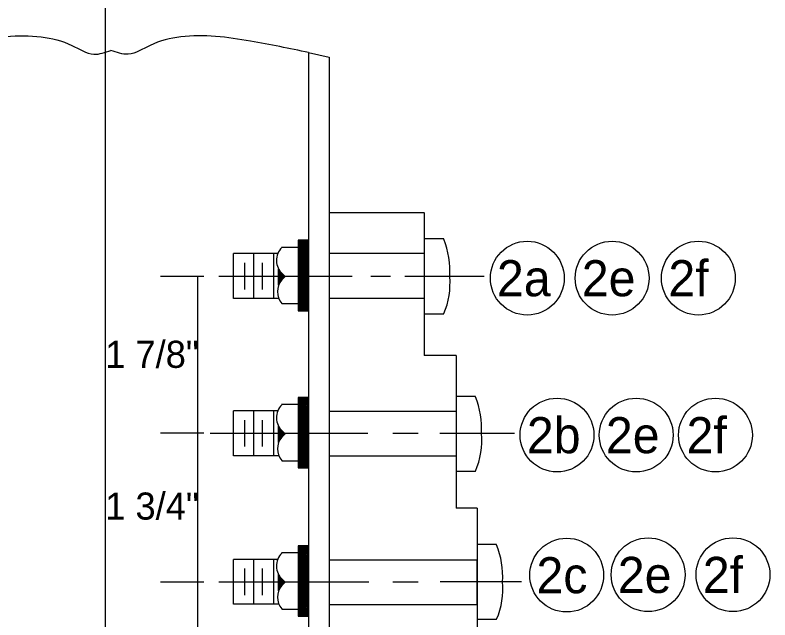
# Model space of a CAD drawing. Extents: x 12.3 to 19.6, y 18.8 to 29.6.
# Drawn here: x 15.033 to 16.703, y 23.308 to 24.647 of the extents above; entities that cross this region are included whole.
import ezdxf

# ---------------------------------------------------------------- set-up
doc = ezdxf.new("R2010")
doc.units = 0
for name, color, linetype in [('BORD-LINE', 7, 'Continuous'), ('DETL-DIMS', 7, 'Continuous'), ('DETL-LINE', 7, 'Continuous')]:
    doc.layers.add(name, color=color, linetype=linetype)

msp = doc.modelspace()

# ---------------------------------------------------------------- linework, layer by layer
at = {"layer": 'BORD-LINE'}
for centre in [(16.1665, 24.0647), (16.3542, 24.0647), (16.5451, 24.0647), (16.2324, 23.7172), (16.4075, 23.7172), (16.5829, 23.7172), (16.2537, 23.407), (16.4339, 23.4079), (16.6216, 23.4079)]:
    msp.add_circle(centre, 0.0817, dxfattribs=at)
at = {"layer": 'DETL-DIMS'}
for p, q in [((15.2325, 25.0229), (15.2325, 22.8206)), ((15.4511, 24.068), (15.3552, 24.068)), ((15.4368, 24.068), (15.4368, 22.9003)), ((15.7792, 24.068), (15.4843, 24.068)), ((15.8638, 24.068), (15.8206, 24.068)), ((16.0712, 24.068), (15.8955, 24.068)), ((15.4511, 23.721), (15.3552, 23.721)), ((15.4645, 23.721), (15.8134, 23.721)), ((15.8691, 23.721), (15.9249, 23.721)), ((15.9728, 23.721), (16.1383, 23.721)), ((15.4511, 23.3913), (15.3552, 23.3913)), ((15.627, 23.3913), (15.4843, 23.3913)), ((15.8158, 23.3913), (15.5089, 23.3913)), ((15.9249, 23.3913), (15.8691, 23.3913)), ((16.1538, 23.3919), (15.9734, 23.3919))]:
    msp.add_line(p, q, dxfattribs=at)
at = {"layer": 'DETL-LINE'}
for p, q in [((15.6827, 24.5643), (15.6827, 22.9003)), ((15.7282, 24.5542), (15.7282, 22.9003)), ((15.9387, 24.2095), (15.7282, 24.2095)), ((15.9387, 24.2095), (15.9387, 24.2101)), ((15.9387, 24.2095), (15.9387, 23.8936)), ((15.6143, 24.119), (15.5167, 24.119)), ((15.5167, 24.0195), (15.5167, 24.119)), ((15.5611, 24.0195), (15.5611, 24.1184)), ((15.6054, 24.0195), (15.6054, 24.1184)), ((15.9387, 24.119), (15.7282, 24.119)), ((15.5412, 24.0398), (15.5412, 24.0986)), ((15.5808, 24.0398), (15.5808, 24.0986)), ((15.6162, 24.0488), (15.6162, 24.0848)), ((15.63, 24.0675), (15.6162, 24.0812)), ((15.63, 24.0668), (15.6162, 24.0795)), ((15.6287, 24.0662), (15.6162, 24.0765)), ((15.6282, 24.0656), (15.6162, 24.074)), ((15.627, 24.0645), (15.6162, 24.0722)), ((15.6263, 24.0632), (15.6162, 24.0705)), ((15.6252, 24.0626), (15.6162, 24.0686)), ((15.624, 24.0615), (15.6162, 24.0668)), ((15.6306, 24.068), (15.6233, 24.0608)), ((15.6306, 24.068), (15.6252, 24.074)), ((15.6228, 24.0602), (15.6162, 24.065)), ((15.6222, 24.0591), (15.6162, 24.0632)), ((15.621, 24.0578), (15.6162, 24.0615)), ((15.6203, 24.0566), (15.6162, 24.0596)), ((15.6198, 24.0555), (15.6162, 24.0578)), ((15.6186, 24.0536), (15.6162, 24.0561)), ((15.618, 24.0525), (15.6162, 24.0542)), ((15.6173, 24.0512), (15.6162, 24.0525)), ((15.6168, 24.0501), (15.6162, 24.0506)), ((15.6168, 24.0195), (15.5167, 24.0195)), ((15.9387, 24.0195), (15.7282, 24.0195)), ((16.0088, 23.8936), (15.9387, 23.8936)), ((16.0088, 23.8936), (16.0088, 23.555)), ((15.6143, 23.7708), (15.5167, 23.7708)), ((15.5167, 23.6712), (15.5167, 23.7708)), ((15.5611, 23.6712), (15.5611, 23.7701)), ((15.6054, 23.6712), (15.6054, 23.7701)), ((16.0088, 23.7695), (15.7282, 23.7695)), ((15.5412, 23.6916), (15.5412, 23.7504)), ((15.5808, 23.6916), (15.5808, 23.7504)), ((15.6162, 23.7006), (15.6162, 23.7365)), ((15.63, 23.7191), (15.6162, 23.7324)), ((15.6293, 23.7186), (15.6162, 23.73)), ((15.6282, 23.7174), (15.6162, 23.7275)), ((15.6276, 23.7168), (15.6162, 23.7251)), ((15.627, 23.7161), (15.6162, 23.7234)), ((15.6258, 23.715), (15.6162, 23.7215)), ((15.6252, 23.7144), (15.6162, 23.7198)), ((15.624, 23.7131), (15.6162, 23.718)), ((15.6228, 23.7114), (15.6162, 23.7161)), ((15.6306, 23.7198), (15.6233, 23.7126)), ((15.6306, 23.7198), (15.6246, 23.7258)), ((15.6216, 23.7101), (15.6162, 23.7144)), ((15.621, 23.7096), (15.6162, 23.7126)), ((15.6203, 23.7084), (15.6162, 23.7114)), ((15.6192, 23.7071), (15.6162, 23.7096)), ((15.6186, 23.706), (15.6162, 23.7078)), ((15.618, 23.7041), (15.6162, 23.706)), ((15.6173, 23.703), (15.6162, 23.7041)), ((15.6168, 23.7018), (15.6162, 23.7024)), ((15.6168, 23.6712), (15.5167, 23.6712)), ((16.0088, 23.6706), (15.7282, 23.6706)), ((16.0556, 23.555), (16.0088, 23.555)), ((16.0556, 23.555), (16.0556, 23.275)), ((15.6143, 23.4417), (15.5167, 23.4417)), ((15.5167, 23.3427), (15.5167, 23.4417)), ((15.5611, 23.3427), (15.5611, 23.4417)), ((15.6054, 23.3427), (15.6054, 23.4417)), ((16.0556, 23.4404), (15.7282, 23.4404)), ((16.0556, 23.4417), (16.0556, 23.3403)), ((16.0556, 23.3409), (16.0556, 23.4392)), ((15.5412, 23.3625), (15.5412, 23.4218)), ((15.5808, 23.3625), (15.5808, 23.4218)), ((15.6162, 23.3721), (15.6162, 23.4081)), ((15.63, 23.3907), (15.6162, 23.4044)), ((15.63, 23.3907), (15.6162, 23.4027)), ((15.6293, 23.3901), (15.6162, 23.4009)), ((15.6287, 23.3889), (15.6162, 23.3979)), ((15.6276, 23.3877), (15.6162, 23.3954)), ((15.6258, 23.3865), (15.6162, 23.3937)), ((15.6252, 23.3853), (15.6162, 23.3913)), ((15.624, 23.3841), (15.6162, 23.3895)), ((15.6228, 23.3829), (15.6162, 23.3877)), ((15.6216, 23.3817), (15.6162, 23.3859)), ((15.621, 23.3805), (15.6162, 23.3835)), ((15.6198, 23.3793), (15.6162, 23.3823)), ((15.6306, 23.3913), (15.6233, 23.3841)), ((15.6306, 23.3913), (15.6246, 23.3973)), ((15.6192, 23.3781), (15.6162, 23.3805)), ((15.6186, 23.3769), (15.6162, 23.3787)), ((15.618, 23.3757), (15.6162, 23.3775)), ((15.6173, 23.3745), (15.6162, 23.3757)), ((15.6168, 23.3733), (15.6162, 23.3739)), ((15.6168, 23.3427), (15.5167, 23.3427)), ((16.0556, 23.3409), (15.7282, 23.3409))]:
    msp.add_line(p, q, dxfattribs=at)
for points in [[(15.6827, 24.5643), (15.7282, 24.5542)], [(15.9818, 24.1507), (15.9818, 24.1514), (15.9387, 24.1514), (15.9387, 23.9859), (15.9818, 23.9859)], [(15.6827, 24.149), (15.6593, 24.149), (15.6593, 23.9925), (15.6827, 23.9925)], [(15.6827, 24.1466), (15.6611, 24.1466), (15.6611, 23.9949), (15.6827, 23.9949)], [(15.6827, 24.1447), (15.6635, 24.1447), (15.6635, 23.9973), (15.6827, 23.9973)], [(15.6827, 24.1424), (15.6653, 24.1424), (15.6653, 23.9991), (15.6827, 23.9991)], [(15.6827, 24.14), (15.6677, 24.14), (15.6677, 24.0015), (15.6827, 24.0015)], [(15.6827, 24.1381), (15.6701, 24.1381), (15.6701, 24.0033), (15.6827, 24.0033)], [(15.6827, 24.1357), (15.672, 24.1357), (15.672, 24.0057), (15.6827, 24.0057)], [(15.6593, 24.1327), (15.6228, 24.1327)], [(15.6827, 24.1334), (15.6743, 24.1334), (15.6743, 24.0081), (15.6827, 24.0081)], [(15.6827, 24.1316), (15.6767, 24.1316), (15.6767, 24.0099), (15.6827, 24.0099)], [(15.6827, 24.1292), (15.6785, 24.1292), (15.6785, 24.0123), (15.6827, 24.0123)], [(15.6827, 24.1274), (15.6809, 24.1274), (15.6809, 24.0147), (15.6827, 24.0147)], [(15.6233, 24.0087), (15.6593, 24.0087)], [(15.6827, 23.8007), (15.6593, 23.8007), (15.6593, 23.6449), (15.6827, 23.6449)], [(16.0519, 23.8019), (16.0519, 23.8025), (16.0088, 23.8025), (16.0088, 23.637), (16.0519, 23.637)], [(15.6593, 23.7845), (15.6228, 23.7845)], [(15.6827, 23.7983), (15.6611, 23.7983), (15.6611, 23.6466), (15.6827, 23.6466)], [(15.6827, 23.7965), (15.6635, 23.7965), (15.6635, 23.649), (15.6827, 23.649)], [(15.6827, 23.7941), (15.6653, 23.7941), (15.6653, 23.6509), (15.6827, 23.6509)], [(15.6827, 23.7917), (15.6677, 23.7917), (15.6677, 23.6532), (15.6827, 23.6532)], [(15.6827, 23.7899), (15.6701, 23.7899), (15.6701, 23.6556), (15.6827, 23.6556)], [(15.6827, 23.7875), (15.672, 23.7875), (15.672, 23.6574), (15.6827, 23.6574)], [(15.6827, 23.7857), (15.6743, 23.7857), (15.6743, 23.6599), (15.6827, 23.6599)], [(15.6827, 23.7833), (15.6761, 23.7833), (15.6761, 23.6622), (15.6827, 23.6622)], [(15.6827, 23.7809), (15.6785, 23.7809), (15.6785, 23.664), (15.6827, 23.664)], [(15.6827, 23.7791), (15.6809, 23.7791), (15.6809, 23.6664), (15.6827, 23.6664)], [(15.6233, 23.6604), (15.6593, 23.6604)], [(15.6827, 23.4722), (15.6593, 23.4722), (15.6593, 23.3158), (15.6827, 23.3158)], [(15.6827, 23.4698), (15.6611, 23.4698), (15.6611, 23.3182), (15.6827, 23.3182)], [(15.6827, 23.4674), (15.6635, 23.4674), (15.6635, 23.3199), (15.6827, 23.3199)], [(15.6827, 23.4656), (15.6653, 23.4656), (15.6653, 23.3224), (15.6827, 23.3224)], [(16.0987, 23.474), (16.0987, 23.4746), (16.0556, 23.4746), (16.0556, 23.3092), (16.0987, 23.3092)], [(15.6593, 23.4561), (15.6228, 23.4561)], [(15.6827, 23.4632), (15.6677, 23.4632), (15.6677, 23.3248), (15.6827, 23.3248)], [(15.6827, 23.4608), (15.6701, 23.4608), (15.6701, 23.3265), (15.6827, 23.3265)], [(15.6827, 23.4591), (15.672, 23.4591), (15.672, 23.3289), (15.6827, 23.3289)], [(15.6827, 23.4566), (15.6743, 23.4566), (15.6743, 23.3313), (15.6827, 23.3313)], [(15.6827, 23.4548), (15.6761, 23.4548), (15.6761, 23.3332), (15.6827, 23.3332)], [(15.6827, 23.4524), (15.6785, 23.4524), (15.6785, 23.3355), (15.6827, 23.3355)], [(15.6827, 23.4501), (15.6809, 23.4501), (15.6809, 23.3373), (15.6827, 23.3373)], [(15.6233, 23.3319), (15.6593, 23.3319)]]:
    msp.add_lwpolyline(points, dxfattribs=at)
for centre, radius, start, end in [((15.8032, 24.0804), 0.192, 356.2821, 21.5569), ((15.6517, 24.1042), 0.0403, 135.1028, 228.1706), ((15.8259, 24.053), 0.1697, 336.8243, 5.0768), ((15.6542, 24.0348), 0.0403, 139.6417, 220.0725), ((15.8734, 23.7315), 0.192, 356.846, 21.5569), ((15.6517, 23.756), 0.0403, 135.1028, 228.1681), ((15.896, 23.704), 0.1697, 336.8243, 5.7166), ((15.6542, 23.6867), 0.0403, 139.7967, 220.0725), ((15.9201, 23.4036), 0.192, 356.6119, 21.5569), ((15.6517, 23.4273), 0.0403, 135.1028, 228.1777), ((15.6542, 23.358), 0.0403, 139.6417, 220.0725), ((15.9427, 23.3761), 0.1697, 336.8243, 5.4509)]:
    msp.add_arc(centre, radius, start, end, dxfattribs=at)
for points in [[(14.8075, 24.5643), (14.9358, 24.5895), (15.0911, 24.5991), (15.1588, 24.58), (15.2074, 24.5607), (15.2451, 24.5691)], [(15.6827, 24.5643), (15.5544, 24.5895), (15.3998, 24.5991), (15.332, 24.58), (15.2835, 24.5607), (15.2451, 24.5691)]]:
    msp.add_spline(points, degree=3, dxfattribs=at)

# ---------------------------------------------------------------- texts
at = {"layer": 'BORD-LINE'}
for s, height, p in [('2a', 0.0799, (16.0994, 24.0246)), ('2e', 0.0799, (16.2871, 24.0246)), ('2f', 0.0799, (16.4787, 24.0246)), ('1 7/8"', 0.06, (15.2326, 23.866)), ('2b', 0.0799, (16.1656, 23.677)), ('2e', 0.0799, (16.3404, 23.677)), ('2f', 0.0799, (16.5189, 23.677)), ('1 3/4"', 0.06, (15.2326, 23.5299)), ('2f', 0.0799, (16.5549, 23.3675)), ('2c', 0.0799, (16.1868, 23.3668)), ('2e', 0.0799, (16.3668, 23.3675))]:
    msp.add_text(s, height=height, dxfattribs=at).set_placement(p)

doc.saveas('drawing.dxf')
